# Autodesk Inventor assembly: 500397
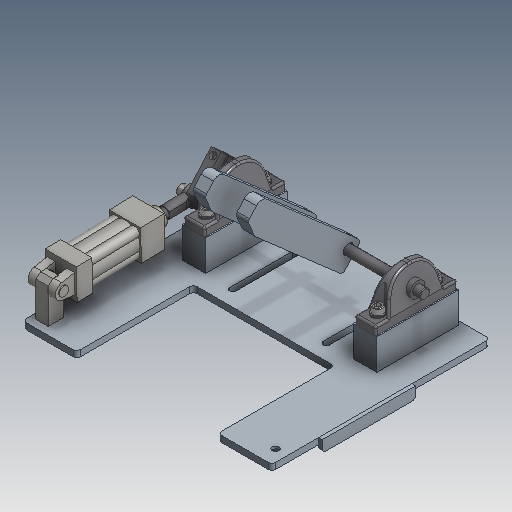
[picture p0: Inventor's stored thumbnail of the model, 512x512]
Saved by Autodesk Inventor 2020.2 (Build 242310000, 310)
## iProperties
Created: 1999-12
Part Number: 500397
Description: ASY,S,CARRIAGE,TRANSFER
Document SubType Name: Assembly
Designer: gpurviance
Mass: 8911.8 g
Surface Area: 5302.32 cm^2
Volume: 2491.53 cm^3
Density: 3.57684 g/cm^3
Control State: 0
Master: False
Checked Out: False
Shininess: 0.0
Length Units: 11269
Angle Units: 11279
Time Units: 11290
Mass Units: 11283
Length Display Precision: 3
Angle Display Precision: 2
Compacted: True
Material Desc: CYL,CLEV,1.5x2.0,0.44-20NF,0.63 ROD
Cutlength: xx
Material_number: A105158
Dimensions: 247,5x355x418,9 mm
Mass: 8,912 kg
DocNumber: 500397.iam
Folder: 01 - Themengebiete\Simplification\01 - Packaging machine\
VDS_Category: 3D Komponenten
Density: 0.0
Volumn: 0.0
Area: 0.0
PropertySet Name: Model Information
Author: gpurviance
Revision Number: -
Title: ASY,S,CARRIAGE,TRANSFER
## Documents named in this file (15)
- D:\07 - DEMODATEN\OTX 2019 - Dataset - UPDATE - Dez2019\Designs\07-Packing machine\500397.iam
- D:\07 - DEMODATEN\OTX 2019 - Dataset - UPDATE - Dez2019\Designs\07-Packing machine\Parts\ADSK-011823.ipt
- D:\07 - DEMODATEN\OTX 2019 - Dataset - UPDATE - Dez2019\Designs\07-Packing machine\500213.iam
- D:\07 - DEMODATEN\OTX 2019 - Dataset - UPDATE - Dez2019\Designs\07-Packing machine\A105158.iam
- D:\07 - DEMODATEN\OTX 2019 - Dataset - UPDATE - Dez2019\Designs\07-Packing machine\Parts\ADSK-011308.ipt
- D:\07 - DEMODATEN\OTX 2019 - Dataset - UPDATE - Dez2019\Designs\07-Packing machine\Parts\ADSK-011302.ipt
- D:\07 - DEMODATEN\OTX 2019 - Dataset - UPDATE - Dez2019\Designs\07-Packing machine\Parts\ADSK-011303.ipt
- D:\07 - DEMODATEN\OTX 2019 - Dataset - UPDATE - Dez2019\Designs\07-Packing machine\Parts\ADSK-011733.ipt
- D:\07 - DEMODATEN\OTX 2019 - Dataset - UPDATE - Dez2019\Designs\07-Packing machine\Parts\ADSK-011310.ipt
- D:\07 - DEMODATEN\OTX 2019 - Dataset - UPDATE - Dez2019\Designs\07-Packing machine\A081742.iam
- D:\07 - DEMODATEN\OTX 2019 - Dataset - UPDATE - Dez2019\Content Center Files\de-DE\ISO 10642(1)\ISO 10642 - M8x20.ipt
- D:\07 - DEMODATEN\OTX 2019 - Dataset - UPDATE - Dez2019\Content Center Files\de-DE\DIN 125-1  B\DIN 125-1 - B 10,5.ipt
- D:\07 - DEMODATEN\OTX 2019 - Dataset - UPDATE - Dez2019\Content Center Files\de-DE\ISO 4762(2)\ISO 4762 - M10 x 30ISO.ipt
- D:\07 - DEMODATEN\OTX 2019 - Dataset - UPDATE - Dez2019\Content Center Files\de-DE\ISO 2491 - A\ISO 2491 - A  5 x 3 x 22.ipt
- D:\07 - DEMODATEN\OTX 2019 - Dataset - UPDATE - Dez2019\Content Center Files\de-DE\ISO 4028\ISO 4028 - M5 x 8 - ISO.ipt
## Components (30 placed, 14 different names)
1. 500213:1 [sub-assembly] — MOVEMENT, Passend:11, Passend:12, Passend:13, Passend:14, Passend:15, Passend:16, Passend:43, Fluchtend:9, Einfügen:8, Passend:64
2. ADSK-011302:1 — Passend:44, Passend:47, Passend:48, Passend:55, Passend:57
3. ADSK-011302:2 — MOVEMENT, Passend:44, Passend:46, Passend:49, Fluchtend:9, Passend:52, Passend:56
4. ADSK-011303:1 — Passend:43, Passend:45, Passend:46, Passend:47, Passend:48, Passend:49, Passend:50, Passend:51, Passend:53, Passend:54, Passend:61, Passend:63, Fluchtend:10
5. ADSK-011308:1 — Passend:11, Passend:12, Passend:13, Passend:21, Fluchtend:8, Passend:22
6. ADSK-011308:2 — Passend:14, Passend:15, Passend:16, Passend:23, Passend:24, Passend:25
7. ADSK-011310:1 — Passend:61, Passend:62, Passend:63, Fluchtend:10
8. A081742:1 [sub-assembly] — Insert:7, Passend:60, Passend:62
9. ADSK-011733:1 — Passend:23, Passend:24, Passend:25, Passend:31, Passend:33
10. ADSK-011733:2 — Passend:21, Fluchtend:8, Passend:22, Passend:27, Passend:29, Passend:45
11. ADSK-011823:1 — Insert:6, Einfügen:8, Passend:64
12. A105158:1 [sub-assembly] — Insert:6, Insert:7, Passend:60
13. ISO 10642 M8x20:1
14. ISO 10642 M8x20:2
15. ISO 10642 M8x20:3
16. ISO 10642 M8x20:4
17. DIN 125-1 B B 10,5:1 — Passend:27, Passend:39, Passend:41
18. DIN 125-1 B B 10,5:2 — Passend:29
19. DIN 125-1 B B 10,5:3 — Passend:31, Passend:35, Passend:37
20. DIN 125-1 B B 10,5:4 — Passend:33
21. ISO 4762 M10 x 30:1 — Passend:35
22. ISO 4762 M10 x 30:2 — Passend:37
23. ISO 4762 M10 x 30:3 — Passend:39
24. ISO 4762 M10 x 30:4 — Passend:41
25. ISO 2491 A A  5 x 3 x 22:1 — Passend:50, Passend:51, Passend:52, Passend:59
26. ISO 2491 A A  5 x 3 x 22:2 — Passend:53, Passend:54, Passend:55, Passend:58
27. ISO 4028 M5 x 8:1 — Passend:56, Passend:59
28. ISO 4028 M5 x 8:2 — Passend:57, Passend:58
29. DIN 125-1 B B 10,5:5 — Einfügen:10
30. ISO 4762 M10 x 30:5 — Einfügen:10
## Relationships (49: Mate 41, Insert 4, Flush 3, Angle 1)
- MOVEMENT [Angle]: 500213:1 ↔ ADSK-011302:2
- Insert:6: ADSK-011823:1 ↔ A105158:1
- Insert:7: A081742:1 ↔ A105158:1
- Passend:11 [Mate]: 500213:1 ↔ ADSK-011308:1
- Passend:12 [Mate]: 500213:1 ↔ ADSK-011308:1
- Passend:13 [Mate]: 500213:1 ↔ ADSK-011308:1
- Passend:14 [Mate]: 500213:1 ↔ ADSK-011308:2
- Passend:15 [Mate]: 500213:1 ↔ ADSK-011308:2
- Passend:16 [Mate]: 500213:1 ↔ ADSK-011308:2
- Passend:21 [Mate]: ADSK-011308:1 ↔ ADSK-011733:2
- Fluchtend:8 [Flush]: ADSK-011308:1 ↔ ADSK-011733:2
- Passend:22 [Mate]: ADSK-011308:1 ↔ ADSK-011733:2
- Passend:23 [Mate]: ADSK-011308:2 ↔ ADSK-011733:1
- Passend:24 [Mate]: ADSK-011308:2 ↔ ADSK-011733:1
- Passend:25 [Mate]: ADSK-011308:2 ↔ ADSK-011733:1
- Passend:27 [Mate]: ADSK-011733:2 ↔ DIN 125-1 B B 10,5:1
- Passend:29 [Mate]: ADSK-011733:2 ↔ DIN 125-1 B B 10,5:2
- Passend:31 [Mate]: ADSK-011733:1 ↔ DIN 125-1 B B 10,5:3
- Passend:33 [Mate]: ADSK-011733:1 ↔ DIN 125-1 B B 10,5:4
- Passend:35 [Mate]: DIN 125-1 B B 10,5:3 ↔ ISO 4762 M10 x 30:1
- Passend:37 [Mate]: DIN 125-1 B B 10,5:3 ↔ ISO 4762 M10 x 30:2
- Passend:39 [Mate]: DIN 125-1 B B 10,5:1 ↔ ISO 4762 M10 x 30:3
- Passend:41 [Mate]: DIN 125-1 B B 10,5:1 ↔ ISO 4762 M10 x 30:4
- Passend:43 [Mate]: 500213:1 ↔ ADSK-011303:1
- Passend:44 [Mate]: ADSK-011302:1 ↔ ADSK-011302:2
- Passend:45 [Mate]: ADSK-011303:1 ↔ ADSK-011733:2
- Passend:46 [Mate]: ADSK-011302:2 ↔ ADSK-011303:1
- Passend:47 [Mate]: ADSK-011302:1 ↔ ADSK-011303:1
- Passend:48 [Mate]: ADSK-011302:1 ↔ ADSK-011303:1
- Passend:49 [Mate]: ADSK-011302:2 ↔ ADSK-011303:1
- Fluchtend:9 [Flush]: 500213:1 ↔ ADSK-011302:2
- Passend:50 [Mate]: ADSK-011303:1 ↔ ISO 2491 A A  5 x 3 x 22:1
- Passend:51 [Mate]: ADSK-011303:1 ↔ ISO 2491 A A  5 x 3 x 22:1
- Passend:52 [Mate]: ADSK-011302:2 ↔ ISO 2491 A A  5 x 3 x 22:1
- Passend:53 [Mate]: ADSK-011303:1 ↔ ISO 2491 A A  5 x 3 x 22:2
- Passend:54 [Mate]: ADSK-011303:1 ↔ ISO 2491 A A  5 x 3 x 22:2
- Passend:55 [Mate]: ADSK-011302:1 ↔ ISO 2491 A A  5 x 3 x 22:2
- Passend:56 [Mate]: ADSK-011302:2 ↔ ISO 4028 M5 x 8:1
- Passend:57 [Mate]: ADSK-011302:1 ↔ ISO 4028 M5 x 8:2
- Passend:58 [Mate]: ISO 2491 A A  5 x 3 x 22:2 ↔ ISO 4028 M5 x 8:2
- Passend:59 [Mate]: ISO 2491 A A  5 x 3 x 22:1 ↔ ISO 4028 M5 x 8:1
- Passend:60 [Mate]: A081742:1 ↔ A105158:1
- Einfügen:8 [Insert]: 500213:1 ↔ ADSK-011823:1
- Passend:61 [Mate]: ADSK-011303:1 ↔ ADSK-011310:1
- Passend:62 [Mate]: ADSK-011310:1 ↔ A081742:1
- Passend:63 [Mate]: ADSK-011303:1 ↔ ADSK-011310:1
- Fluchtend:10 [Flush]: ADSK-011303:1 ↔ ADSK-011310:1
- Einfügen:10 [Insert]: DIN 125-1 B B 10,5:5 ↔ ISO 4762 M10 x 30:5
- Passend:64 [Mate]: 500213:1 ↔ ADSK-011823:1
